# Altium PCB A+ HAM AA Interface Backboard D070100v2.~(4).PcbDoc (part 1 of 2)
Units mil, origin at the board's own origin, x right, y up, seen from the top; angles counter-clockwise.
Board outline 2600 x 10000 mil, 6 copper layers (Top Layer, InternalPlane1, MidLayer1, InternalPlane3, InternalPlane4, Bottom Layer), stack 92.2 mil thick; 10 components, 66 nets, 166 pads, 1741 vias.
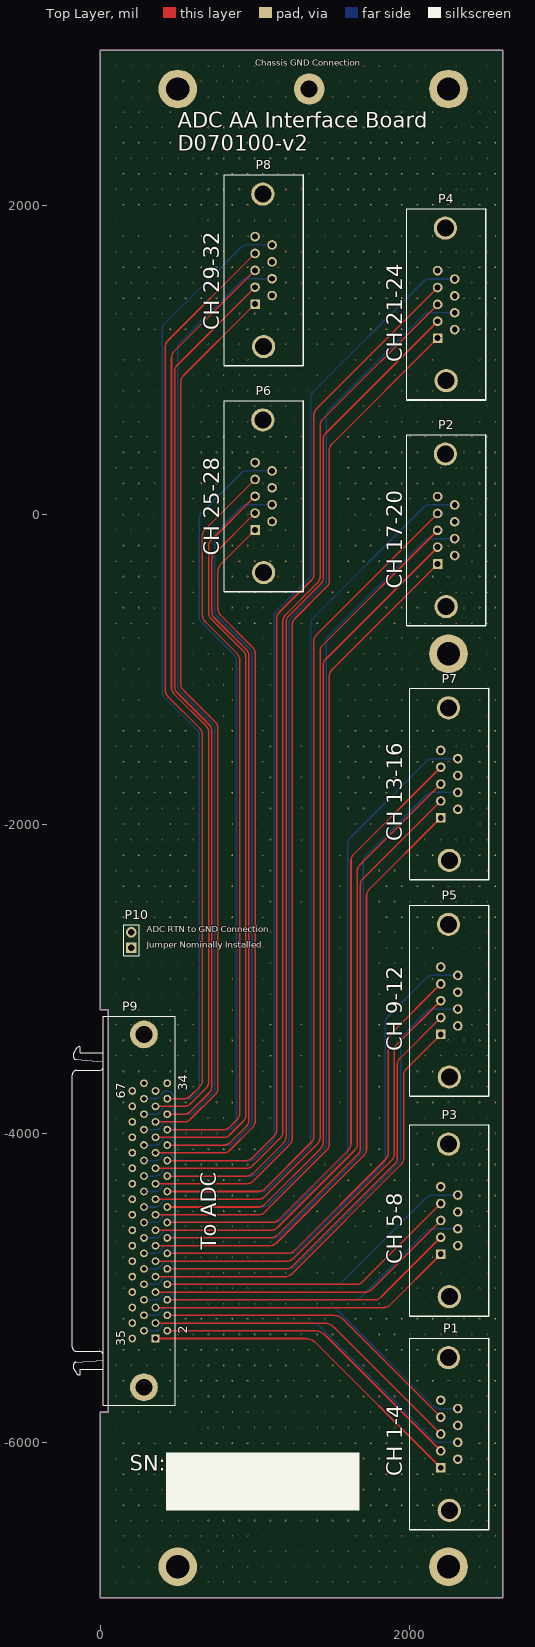
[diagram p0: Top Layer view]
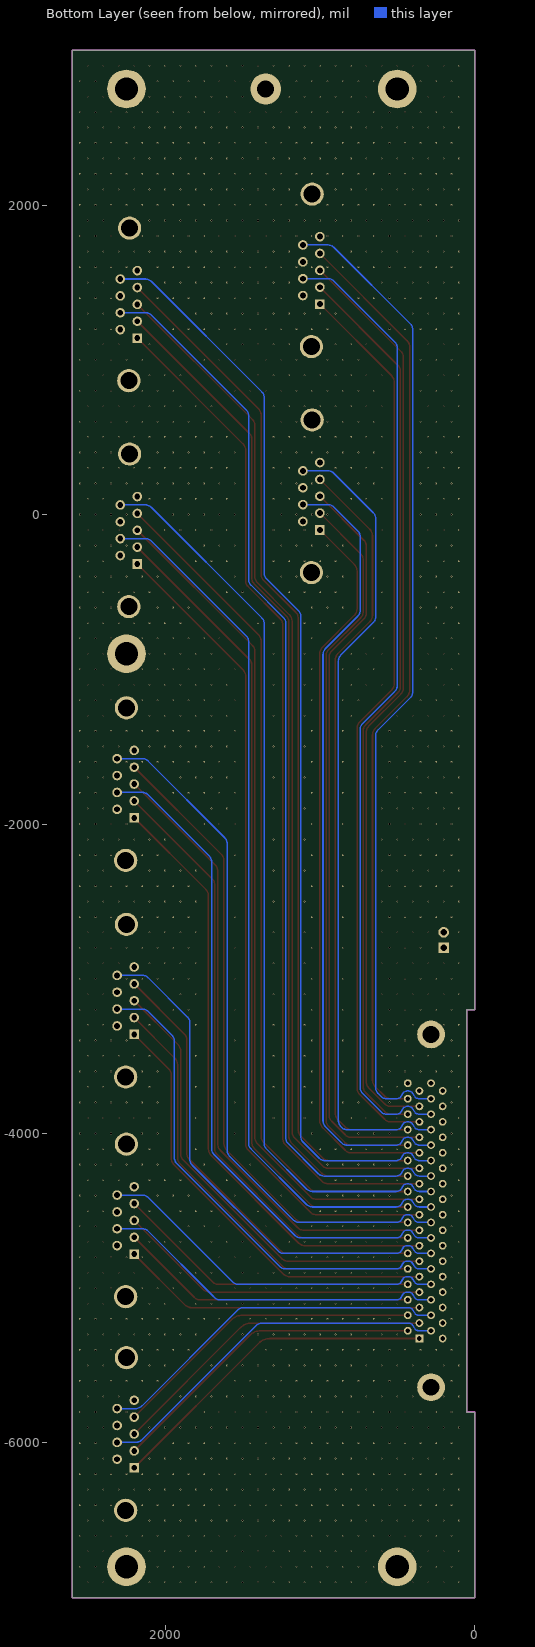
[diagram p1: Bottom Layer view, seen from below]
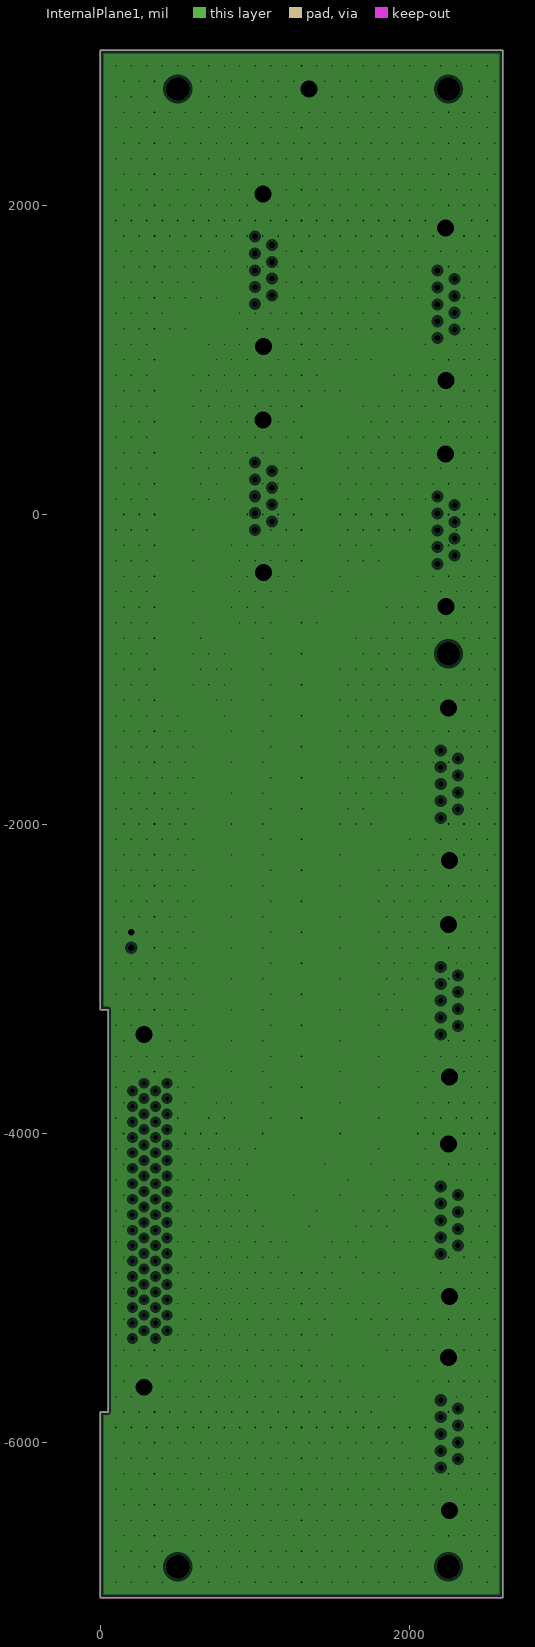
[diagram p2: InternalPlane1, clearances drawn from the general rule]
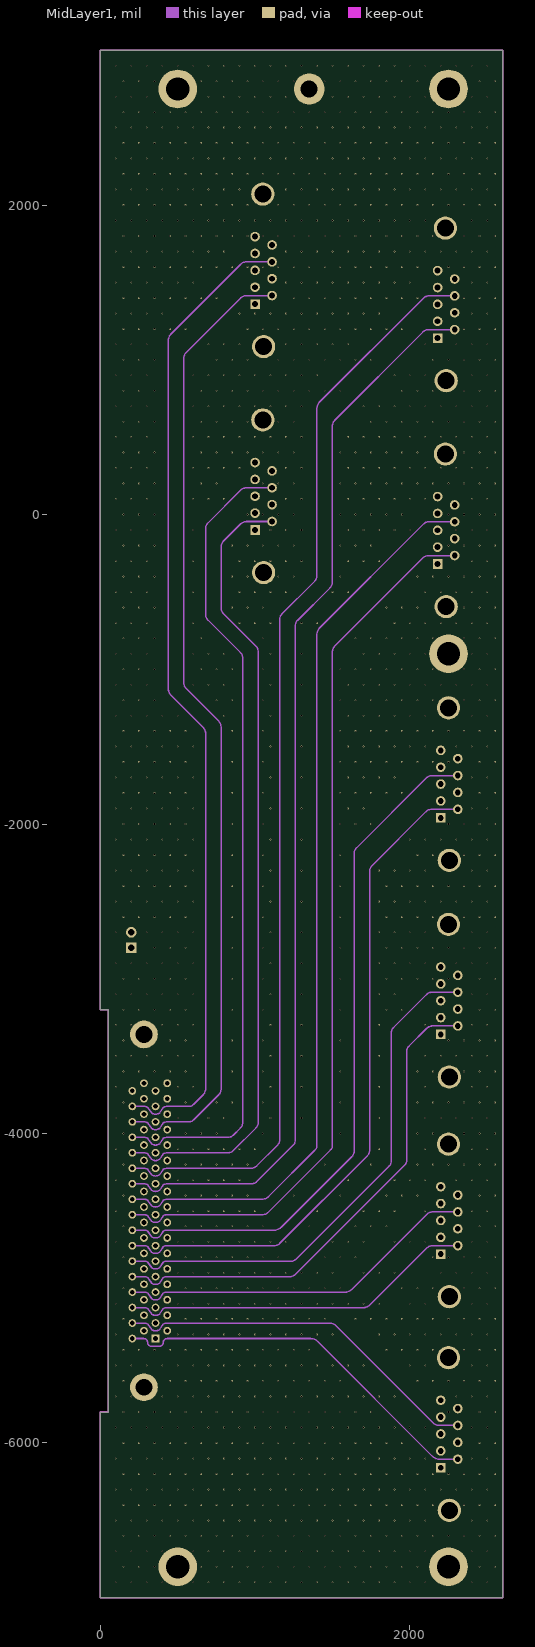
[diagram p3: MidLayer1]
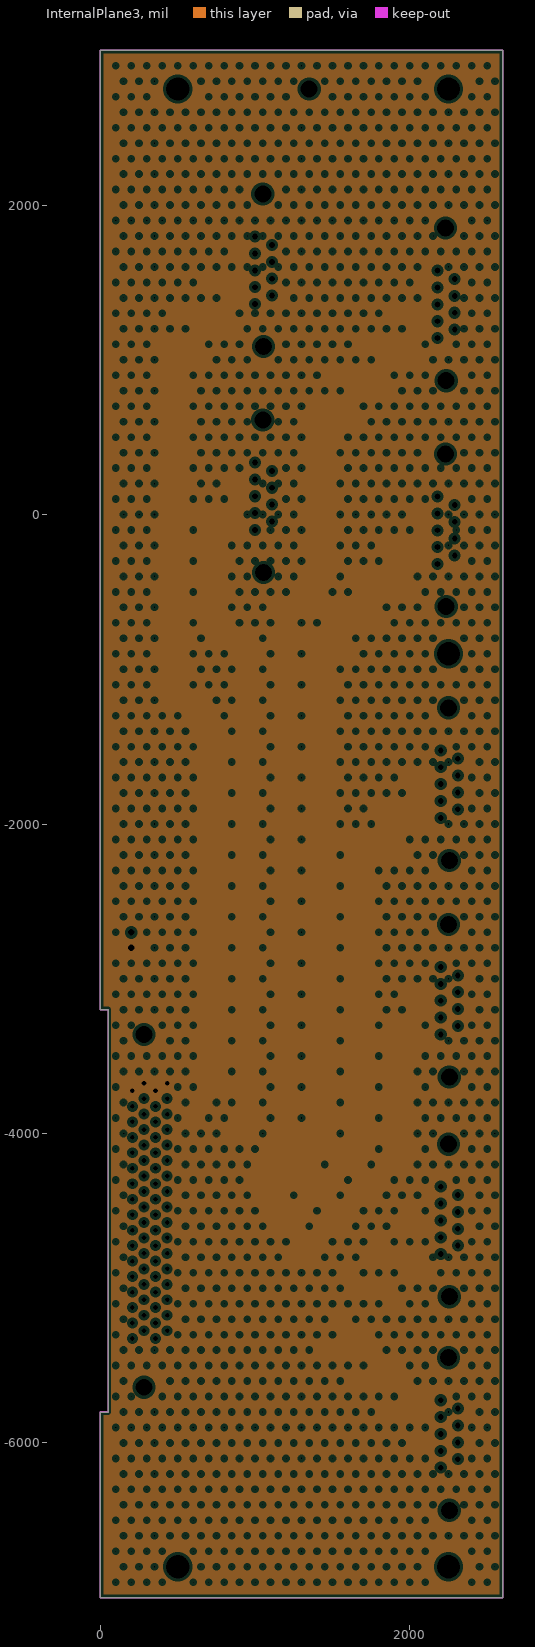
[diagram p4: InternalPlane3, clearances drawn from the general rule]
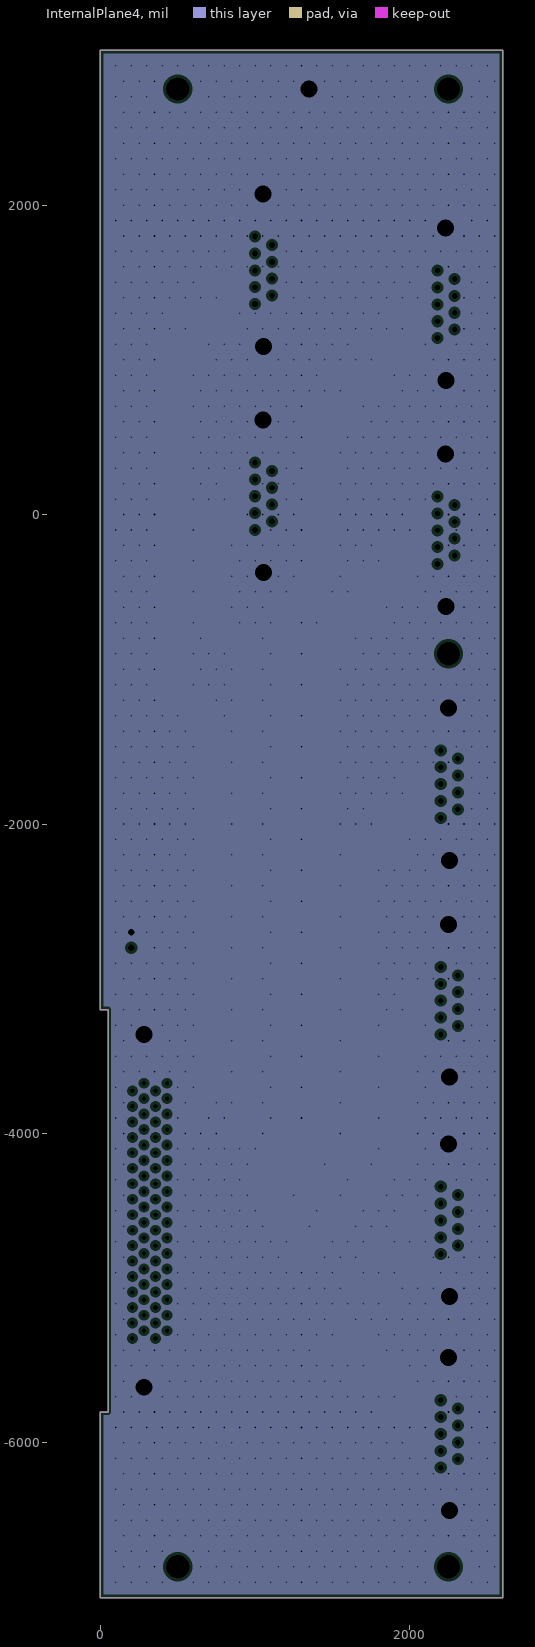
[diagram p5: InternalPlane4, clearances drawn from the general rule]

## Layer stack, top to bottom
Top Solder: solder mask 0.4, Solder Resist, Dk 3.5
Top Layer: signal copper 1.4
Dielectric1: core 15, FR-4, Dk 4.2
InternalPlane1: plane copper 1.4
Dielectric 6: prepreg 19.4, FR-4, Dk 4.2
MidLayer1: signal copper 1.4
Dielectric3: core 15, FR-4, Dk 4.2
InternalPlane3: plane copper 1.4
Dielectric4: prepreg 19.4, FR-4, Dk 4.2
InternalPlane4: plane copper 1.4
Dielectric5: core 15, FR-4, Dk 4.2
Bottom Layer: signal copper 1.4
Bottom Solder: solder mask 0.4, Solder Resist, Dk 3.5

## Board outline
0,-7000 0,-5800 50,-5800 50,-3200 0,-3200 0,3000 2600,3000 2600,-7000

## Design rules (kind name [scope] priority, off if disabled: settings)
Clearance [All] p1: gap=10 ignorepadtopadclearanceinfootprint=FALSE except(0: Arc-Hole Track-Hole SMDPad-Hole THPad-Hole Via-Hole Fill-Hole Poly-Hole Region-Hole Text-Hole)
FabricationTestPointUsage TestPointUsage [All] p1: valid=0 allowmultiple=FALSE
FabricationTestpoint Testpoint [All] p1: side=3 testpointundercomponent=TRUE minsize=40 maxsize=100 preferedsize=60 minholesize=0 maxholesize=40 preferedholesize=32 testpointgrid=1 allowsidetop=TRUE allowsidebottom=TRUE usegrid=TRUE gridtolerance=0.01
HoleSize [All] p1: absolutevalues=TRUE maxlimit=200 minlimit=1 maxpercent=80.000 minpercent=20.000
PlaneClearance [All] p1: clearance=20
PlaneConnect [All] p1: planeconnectstyle=Relief reliefexpansion=20 reliefentries=4 reliefconductorwidth=10 reliefairgap=10
PolygonConnect [All] p1: connectstyle=Relief reliefconductorwidth=10 reliefentries=4 polygonreliefangle="90 Angle" airgapwidth=10
RoutingVias [All] p1: holewidth=20 width=40 viastyle="Through Hole" minholewidth=20 minwidth=40 maxholewidth=28 maxwidth=50
SolderMaskExpansion [All] p1: expansion=4
Width [All] p1: maxlimit=100 minlimit=10 preferedwidth=10
25 further rules are at their usual default settings.

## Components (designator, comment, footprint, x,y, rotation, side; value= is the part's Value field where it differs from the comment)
P1 "D9M" DB9/M 2200,-6160 r270 top
P2 "D9M" DB9/M 2180,-320 r270 top
P3 "D9M" DB9/M 2200,-4780 r270 top
P4 "D9M" DB9/M 2180,1140 r270 top
P5 "D9M" DB9/M 2200,-3360 r270 top
P6 "D9M" DB9/M 1000,-100 r270 top
P7 "D9M" DB9/M 2200,-1960 r270 top
P8 "D9M" DB9/M 1000,1360 r270 top
P9 "787082-7" 787082-7 20,-4500 r90 top
P10 "Header 2" HDR1X2 200,-2800 r90 top

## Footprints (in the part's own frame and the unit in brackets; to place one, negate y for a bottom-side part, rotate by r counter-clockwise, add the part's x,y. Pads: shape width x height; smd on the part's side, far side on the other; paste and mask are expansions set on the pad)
787082-7 [mm] "Connector; D Subminiature 050 Series; 68 Position; Right Angle"
  rect 1.27x1.27 hole 0.762: 1(-20.955,-8.555)
  round 1.27 hole 0.762: 2(-19.685,-10.46) 3(-18.415,-8.555) 4(-17.145,-10.46) 5(-15.875,-8.555) 6(-14.605,-10.46) 7(-13.335,-8.555) 8(-12.065,-10.46) 9(-10.795,-8.555) 10(-9.525,-10.46) 11(-8.255,-8.555) 12(-6.985,-10.46) 13(-5.715,-8.555) 14(-4.445,-10.46) 15(-3.175,-8.555) 16(-1.905,-10.46) 17(-0.635,-8.555) 18(0.635,-10.46) 19(1.905,-8.555) 20(3.175,-10.46) 21(4.445,-8.555) 22(5.715,-10.46) 23(6.985,-8.555) 24(8.255,-10.46) 25(9.525,-8.555) 26(10.795,-10.46) 27(12.065,-8.555) 28(13.335,-10.46) 29(14.605,-8.555) 30(15.875,-10.46) 31(17.145,-8.555) 32(18.415,-10.46) 33(19.685,-8.555) 34(20.955,-10.46) 35(-20.955,-4.745) 36(-19.685,-6.65) 37(-18.415,-4.745) 38(-17.145,-6.65) 39(-15.875,-4.745) 40(-14.605,-6.65) 41(-13.335,-4.745) 42(-12.065,-6.65) 43(-10.795,-4.745) 44(-9.525,-6.65) 45(-8.255,-4.745) 46(-6.985,-6.65) 47(-5.715,-4.745) 48(-4.445,-6.65) 49(-3.175,-4.745) 50(-1.905,-6.65) 51(-0.635,-4.745) 52(0.635,-6.65) 53(1.905,-4.745) 54(3.175,-6.65) 55(4.445,-4.745) 56(5.715,-6.65) 57(6.985,-4.745) 58(8.255,-6.65) 59(9.525,-4.745) 60(10.795,-6.65) 61(12.065,-4.745) 62(13.335,-6.65) 63(14.605,-4.745) 64(15.875,-6.65) 65(17.145,-4.745) 66(18.415,-6.65) 67(19.685,-4.745) 68(20.955,-6.65)
  round 4.55 hole 2.77: 69(-28.955,-6.65) 70(28.955,-6.65)
  silkscreen extent -31.95,-11.76 31.95,5.11, body extent -31.94,-11.79 31.94,5.08, height 9.51
DB9/M [mil]
  round 150 hole 110: 0(-711,50) 0(275,55)
  rect 62x62 hole 38: 1(0,0)
  round 62 hole 38: 2(-109,0) 3(-218,0) 4(-327,0) 5(-436,0) 6(-55,110) 7(-164,110) 8(-273,110) 9(-382,110)
  silkscreen extent -836,-200 400,310, body extent -827,-194 389,302, height 470
HDR1X2 [mm] "Connector; Header; 2 Position"
  rect 1.75x1.75 hole 1.1: 1(0,0)
  round 1.75 hole 1.1: 2(2.54,0)
  silkscreen extent -1.27,-1.27 3.81,1.27, body extent -1.14,-1.19 3.68,1.15, height 10.8

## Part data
P1 P2 P3 P4 P5 P6 P7 P8: "9 Position D-Sub Plug, Male Pins Connector", Color=Black, Current Rating=6A, Flammability Rating="UL94 V-0", Manufacturer="TE Connectivity", Manufacturer Part Number=5747871-8, Max Operating Temperature=105°C, Max Supply Voltage (AC)=250V, Max Voltage Rating (DC)=250.25kV, Min Operating Temperature=-55°C, Package Quantity=17, Supplier Part Number 1=A32035-ND, Voltage Rating=125V
P9: "Receptacle Assembly, Shielded, Right Angle, AMPLIMITE", PackageDocument=13-Jan-2000
P10: "Header, 2-Pin", Part Number=WM4200

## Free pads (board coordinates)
  round 200 hole 110: 0(1350,2750)
  round 250 hole 150: 0(2250,-6800) 1(2250,2750) 2(500,2750) 3(500,-6800) 4(2250,-900)

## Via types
v1: diameter 12, hole 10, Top Layer to Bottom Layer, 1741 vias

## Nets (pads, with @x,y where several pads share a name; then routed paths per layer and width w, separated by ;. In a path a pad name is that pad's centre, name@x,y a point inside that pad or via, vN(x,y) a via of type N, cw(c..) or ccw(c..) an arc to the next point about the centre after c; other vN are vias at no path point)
GND: P1.0 P2.0 P3.0 P4.0 P5.0 P6.0 P7.0 P8.0 P9.69 P9.70 P10.2 pad.0@1350,2750
  other v1: 100,-6900 200,-6900 300,-6900 400,-6900 600,-6900 700,-6900 800,-6900 900,-6900 1000,-6900 1100,-6900 1200,-6900 1300,-6900 1400,-6900 1500,-6900 1600,-6900 1700,-6900 1800,-6900 1900,-6900 2000,-6900 2100,-6900 2400,-6900 2500,-6900 150,-6800 250,-6800 350,-6800 650,-6800 750,-6800 850,-6800 950,-6800 1050,-6800 1150,-6800 1250,-6800 1350,-6800 1450,-6800 1550,-6800 1650,-6800 1750,-6800 1850,-6800 1950,-6800 2050,-6800 2450,-6800 2550,-6800 100,-6700 200,-6700 300,-6700 400,-6700 600,-6700 700,-6700 800,-6700 900,-6700 1000,-6700 1100,-6700 1200,-6700 1300,-6700 1400,-6700 1500,-6700 1600,-6700 1700,-6700 1800,-6700 1900,-6700 2000,-6700 2100,-6700 2400,-6700 2500,-6700 150,-6600 250,-6600 350,-6600 450,-6600 550,-6600 650,-6600 750,-6600 850,-6600 950,-6600 1050,-6600 1150,-6600 1250,-6600 1350,-6600 1450,-6600 1550,-6600 1650,-6600 1750,-6600 1850,-6600 1950,-6600 2050,-6600 2150,-6600 2250,-6600 2350,-6600 2450,-6600 2550,-6600 100,-6500 200,-6500 300,-6500 400,-6500 500,-6500 600,-6500 700,-6500 800,-6500 900,-6500 1000,-6500 1100,-6500 1200,-6500 1300,-6500 1400,-6500 1500,-6500 1600,-6500 1700,-6500 1800,-6500 1900,-6500 2000,-6500 2100,-6500 2400,-6500 2500,-6500 150,-6400 250,-6400 350,-6400 450,-6400 550,-6400 650,-6400 750,-6400 850,-6400 950,-6400 1050,-6400 1150,-6400 1250,-6400 1350,-6400 1450,-6400 1550,-6400 1650,-6400 1750,-6400 1850,-6400 1950,-6400 2050,-6400 2150,-6400 2350,-6400 2450,-6400 2550,-6400 100,-6300 200,-6300 300,-6300 400,-6300 500,-6300 600,-6300 700,-6300 800,-6300 900,-6300 1000,-6300 1100,-6300 1200,-6300 1300,-6300 1400,-6300 1500,-6300 1600,-6300 1700,-6300 1800,-6300 1900,-6300 2000,-6300 2100,-6300 2200,-6300 2300,-6300 2400,-6300 2500,-6300 150,-6200 250,-6200 350,-6200 450,-6200 550,-6200 650,-6200 750,-6200 850,-6200 950,-6200 1050,-6200 1150,-6200 1250,-6200 1350,-6200 1450,-6200 1550,-6200 1650,-6200 1750,-6200 1850,-6200 1950,-6200 2050,-6200 2150,-6200 2250,-6200 2350,-6200 2450,-6200 2550,-6200 100,-6100 200,-6100 300,-6100 400,-6100 500,-6100 600,-6100 700,-6100 800,-6100 900,-6100 1000,-6100 1100,-6100 1200,-6100 1300,-6100 1400,-6100 1500,-6100 1600,-6100 1700,-6100 1800,-6100 1900,-6100 2000,-6100 2100,-6100 2400,-6100 2500,-6100 150,-6000 250,-6000 350,-6000 450,-6000 550,-6000 650,-6000 750,-6000 850,-6000 950,-6000 1050,-6000 1150,-6000 1250,-6000 1350,-6000 1450,-6000 1550,-6000 1650,-6000 1750,-6000 1850,-6000 1950,-6000 2450,-6000 2550,-6000 100,-5900 200,-5900 300,-5900 400,-5900 500,-5900 600,-5900 700,-5900 800,-5900 900,-5900 1000,-5900 1100,-5900 1200,-5900 1300,-5900 1400,-5900 1500,-5900 1600,-5900 1700,-5900 1800,-5900 1900,-5900 2000,-5900 2100,-5900 2400,-5900 2500,-5900 150,-5800 250,-5800 350,-5800 450,-5800 550,-5800 650,-5800 750,-5800 850,-5800 950,-5800 1050,-5800 1150,-5800 1250,-5800 1350,-5800 1450,-5800 1550,-5800 1650,-5800 1750,-5800 2250,-5800 2450,-5800 2550,-5800 100,-5700 200,-5700 400,-5700 500,-5700 600,-5700 700,-5700 800,-5700 900,-5700 1000,-5700 1100,-5700 1200,-5700 1300,-5700 1400,-5700 1500,-5700 1600,-5700 1700,-5700 1800,-5700 1900,-5700 2300,-5700 2400,-5700 2500,-5700 150,-5600 450,-5600 550,-5600 650,-5600 750,-5600 850,-5600 950,-5600 1050,-5600 1150,-5600 1250,-5600 1350,-5600 1450,-5600 1550,-5600 2050,-5600 2150,-5600 2250,-5600 2350,-5600 2450,-5600 2550,-5600 100,-5500 200,-5500 300,-5500 400,-5500 500,-5500 600,-5500 700,-5500 800,-5500 900,-5500 1000,-5500 1100,-5500 1200,-5500 1300,-5500 1400,-5500 1500,-5500 1600,-5500 1700,-5500 2000,-5500 2100,-5500 2400,-5500 2500,-5500 150,-5400 250,-5400 350,-5400 450,-5400 550,-5400 650,-5400 750,-5400 850,-5400 950,-5400 1050,-5400 1150,-5400 1250,-5400 1350,-5400 1850,-5400 1950,-5400 2050,-5400 2150,-5400 2350,-5400 2450,-5400 2550,-5400 100,-5300 500,-5300 600,-5300 700,-5300 800,-5300 900,-5300 1000,-5300 1100,-5300 1200,-5300 1300,-5300 1400,-5300 1500,-5300 1800,-5300 1900,-5300 2000,-5300 2100,-5300 2200,-5300 2300,-5300 2400,-5300 2500,-5300 150,-5200 550,-5200 650,-5200 750,-5200 850,-5200 950,-5200 1050,-5200 1150,-5200 1250,-5200 1350,-5200 1450,-5200 1650,-5200 1750,-5200 1850,-5200 1950,-5200 2050,-5200 2150,-5200 2250,-5200 2350,-5200 2450,-5200 2550,-5200 100,-5100 500,-5100 600,-5100 700,-5100 800,-5100 900,-5100 1000,-5100 1100,-5100 1200,-5100 1300,-5100 1400,-5100 1500,-5100 1600,-5100 1700,-5100 1800,-5100 2000,-5100 2100,-5100 2400,-5100 2500,-5100 150,-5000 550,-5000 650,-5000 750,-5000 850,-5000 950,-5000 1050,-5000 1150,-5000 1250,-5000 1350,-5000 1450,-5000 1550,-5000 1950,-5000 2050,-5000 2150,-5000 2350,-5000 2450,-5000 2550,-5000 100,-4900 500,-4900 600,-4900 700,-4900 800,-4900 900,-4900 1000,-4900 1100,-4900 1200,-4900 1300,-4900 1400,-4900 1500,-4900 1700,-4900 1800,-4900 1900,-4900 2200,-4900 2300,-4900 2400,-4900 2500,-4900 150,-4800 550,-4800 650,-4800 750,-4800 850,-4800 950,-4800 1050,-4800 1150,-4800 1450,-4800 1550,-4800 1650,-4800 2150,-4800 2250,-4800 2350,-4800 2450,-4800 2550,-4800 100,-4700 500,-4700 600,-4700 700,-4700 800,-4700 900,-4700 1000,-4700 1100,-4700 1200,-4700 1500,-4700 1600,-4700 1700,-4700 1900,-4700 2000,-4700 2100,-4700 2400,-4700 2500,-4700 150,-4600 550,-4600 650,-4600 750,-4600 850,-4600 950,-4600 1050,-4600 1350,-4600 1650,-4600 1750,-4600 1850,-4600 2450,-4600 2550,-4600 100,-4500 500,-4500 600,-4500 700,-4500 800,-4500 900,-4500 1000,-4500 1400,-4500 1700,-4500 1800,-4500 1900,-4500 2100,-4500 2400,-4500 2500,-4500 150,-4400 550,-4400 650,-4400 750,-4400 850,-4400 950,-4400 1250,-4400 1550,-4400 1850,-4400 1950,-4400 2050,-4400 2450,-4400 2550,-4400 100,-4300 500,-4300 600,-4300 700,-4300 800,-4300 900,-4300 1600,-4300 1900,-4300 2000,-4300 2100,-4300 2300,-4300 2400,-4300 2500,-4300 150,-4200 550,-4200 650,-4200 750,-4200 850,-4200 950,-4200 1450,-4200 1750,-4200 2050,-4200 2150,-4200 2250,-4200 2350,-4200 2450,-4200 2550,-4200 100,-4100 500,-4100 600,-4100 700,-4100 800,-4100 900,-4100 1000,-4100 1800,-4100 2100,-4100 2400,-4100 2500,-4100 150,-4000 550,-4000 650,-4000 750,-4000 1050,-4000 1550,-4000 2050,-4000 2150,-4000 2350,-4000 2450,-4000 2550,-4000 100,-3900 500,-3900 700,-3900 800,-3900 1100,-3900 1300,-3900 1800,-3900 2100,-3900 2200,-3900 2300,-3900 2400,-3900 2500,-3900 150,-3800 550,-3800 750,-3800 850,-3800 1050,-3800 1550,-3800 2050,-3800 2150,-3800 2250,-3800 2350,-3800 2450,-3800 2550,-3800 100,-3700 500,-3700 600,-3700 1100,-3700 1300,-3700 1800,-3700 2100,-3700 2400,-3700 2500,-3700 150,-3600 250,-3600 350,-3600 450,-3600 550,-3600 850,-3600 1050,-3600 1550,-3600 2050,-3600 2150,-3600 2350,-3600 2450,-3600 2550,-3600 100,-3500 200,-3500 300,-3500 400,-3500 500,-3500 600,-3500 1100,-3500 1300,-3500 1800,-3500 2100,-3500 2200,-3500 2300,-3500 2400,-3500 2500,-3500 150,-3400 450,-3400 550,-3400 850,-3400 1050,-3400 1550,-3400 2250,-3400 2350,-3400 2450,-3400 2550,-3400 100,-3300 200,-3300 400,-3300 500,-3300 600,-3300 1100,-3300 1300,-3300 1800,-3300 2100,-3300 2400,-3300 2500,-3300 150,-3200 250,-3200 350,-3200 450,-3200 550,-3200 850,-3200 1050,-3200 1550,-3200 1850,-3200 1950,-3200 2450,-3200 2550,-3200 100,-3100 200,-3100 300,-3100 400,-3100 500,-3100 600,-3100 1100,-3100 1300,-3100 1800,-3100 1900,-3100 2400,-3100 2500,-3100 150,-3000 250,-3000 350,-3000 450,-3000 550,-3000 850,-3000 1050,-3000 1550,-3000 1850,-3000 1950,-3000 2050,-3000 2150,-3000 2250,-3000 2450,-3000 2550,-3000 100,-2900 200,-2900 300,-2900 400,-2900 500,-2900 600,-2900 1100,-2900 1300,-2900 1800,-2900 1900,-2900 2000,-2900 2100,-2900 2300,-2900 2400,-2900 2500,-2900 350,-2800 450,-2800 550,-2800 850,-2800 1050,-2800 1550,-2800 1850,-2800 1950,-2800 2050,-2800 2150,-2800 2250,-2800 2350,-2800 2450,-2800 2550,-2800 100,-2700 300,-2700 400,-2700 500,-2700 600,-2700 1100,-2700 1300,-2700 1800,-2700 1900,-2700 2000,-2700 2100,-2700 2400,-2700 2500,-2700 150,-2600 250,-2600 350,-2600 450,-2600 550,-2600 850,-2600 1050,-2600 1550,-2600 1850,-2600 1950,-2600 2050,-2600 2150,-2600 2350,-2600 2450,-2600 2550,-2600 100,-2500 200,-2500 300,-2500 400,-2500 500,-2500 600,-2500 1100,-2500 1300,-2500 1800,-2500 1900,-2500 2000,-2500 2100,-2500 2200,-2500 2300,-2500 2400,-2500 2500,-2500 150,-2400 250,-2400 350,-2400 450,-2400 550,-2400 850,-2400 1050,-2400 1550,-2400 1850,-2400 1950,-2400 2050,-2400 2150,-2400 2250,-2400 2350,-2400 2450,-2400 2550,-2400 100,-2300 200,-2300 300,-2300 400,-2300 500,-2300 600,-2300 1100,-2300 1300,-2300 1800,-2300 1900,-2300 2000,-2300 2100,-2300 2400,-2300 2500,-2300 150,-2200 250,-2200 350,-2200 450,-2200 550,-2200 850,-2200 1050,-2200 1550,-2200 2050,-2200 2150,-2200 2350,-2200 2450,-2200 2550,-2200 100,-2100 200,-2100 300,-2100 400,-2100 500,-2100 600,-2100 1100,-2100 1300,-2100 2000,-2100 2100,-2100 2200,-2100 2300,-2100 2400,-2100 2500,-2100 150,-2000 250,-2000 350,-2000 450,-2000 550,-2000 850,-2000 1050,-2000 1550,-2000 1650,-2000 1750,-2000 2250,-2000 2350,-2000 2450,-2000 2550,-2000 100,-1900 200,-1900 300,-1900 400,-1900 500,-1900 600,-1900 1100,-1900 1300,-1900 1600,-1900 1700,-1900 2400,-1900 2500,-1900 150,-1800 250,-1800 350,-1800 450,-1800 550,-1800 850,-1800 1050,-1800 1550,-1800 1650,-1800 1750,-1800 1850,-1800 1950,-1800 2450,-1800 2550,-1800 100,-1700 200,-1700 300,-1700 400,-1700 500,-1700 600,-1700 1100,-1700 1300,-1700 1600,-1700 1700,-1700 1800,-1700 1900,-1700 2400,-1700 2500,-1700 150,-1600 250,-1600 350,-1600 450,-1600 550,-1600 850,-1600 1050,-1600 1550,-1600 1650,-1600 1750,-1600 1850,-1600 1950,-1600 2050,-1600 2150,-1600 2250,-1600 2450,-1600 2550,-1600 100,-1500 200,-1500 300,-1500 400,-1500 500,-1500 600,-1500 1100,-1500 1300,-1500 1600,-1500 1700,-1500 1800,-1500 1900,-1500 2000,-1500 2100,-1500 2300,-1500 2400,-1500 2500,-1500 150,-1400 250,-1400 350,-1400 450,-1400 550,-1400 850,-1400 1050,-1400 1550,-1400 1650,-1400 1750,-1400 1850,-1400 1950,-1400 2050,-1400 2150,-1400 2250,-1400 2350,-1400 2450,-1400 2550,-1400 100,-1300 200,-1300 300,-1300 400,-1300 500,-1300 800,-1300 1100,-1300 1300,-1300 1600,-1300 1700,-1300 1800,-1300 1900,-1300 2000,-1300 2100,-1300 2400,-1300 2500,-1300 150,-1200 250,-1200 350,-1200 750,-1200 850,-1200 1050,-1200 1550,-1200 1650,-1200 1750,-1200 1850,-1200 1950,-1200 2050,-1200 2150,-1200 2350,-1200 2450,-1200 2550,-1200 100,-1100 200,-1100 300,-1100 600,-1100 700,-1100 800,-1100 1100,-1100 1300,-1100 1600,-1100 1700,-1100 1800,-1100 1900,-1100 2000,-1100 2100,-1100 2200,-1100 2300,-1100 2400,-1100 2500,-1100 150,-1000 250,-1000 350,-1000 650,-1000 750,-1000 850,-1000 1050,-1000 1550,-1000 1650,-1000 1750,-1000 1850,-1000 1950,-1000 2050,-1000 2150,-1000 2350,-1000 2450,-1000 2550,-1000 100,-900 200,-900 300,-900 600,-900 700,-900 800,-900 1100,-900 1300,-900 1700,-900 1800,-900 1900,-900 2000,-900 2100,-900 2400,-900 2500,-900 150,-800 250,-800 350,-800 650,-800 1050,-800 1650,-800 1750,-800 1850,-800 1950,-800 2050,-800 2150,-800 2350,-800 2450,-800 2550,-800 100,-700 200,-700 300,-700 600,-700 900,-700 1000,-700 1100,-700 1300,-700 1400,-700 1900,-700 2000,-700 2100,-700 2200,-700 2300,-700 2400,-700 2500,-700 150,-600 250,-600 350,-600 850,-600 950,-600 1050,-600 1850,-600 1950,-600 2050,-600 2350,-600 2450,-600 2550,-600 100,-500 200,-500 300,-500 600,-500 900,-500 1000,-500 1100,-500 1200,-500 1500,-500 1600,-500 2100,-500 2200,-500 2300,-500 2400,-500 2500,-500 150,-400 250,-400 350,-400 850,-400 950,-400 1150,-400 1250,-400 1550,-400 2050,-400 2150,-400 2250,-400 2350,-400 2450,-400 2550,-400 100,-300 200,-300 300,-300 600,-300 900,-300 1000,-300 1100,-300 1200,-300 1300,-300 1600,-300 1700,-300 1800,-300 2400,-300 2500,-300 150,-200 250,-200 350,-200 850,-200 950,-200 1050,-200 1150,-200 1250,-200 1550,-200 1650,-200 1750,-200 2250,-200 2350,-200 2450,-200 2550,-200 100,-100 200,-100 300,-100 600,-100 1100,-100 1200,-100 1300,-100 1600,-100 1700,-100 1800,-100 1900,-100 2000,-100 2300,-100 2400,-100 2500,-100 150,0 250,0 350,0 950,0 1050,0 1150,0 1250,0 1550,0 1650,0 1750,0 1850,0 1950,0 2250,0 2350,0 2450,0 2550,0 100,100 200,100 300,100 600,100 700,100 800,100 1200,100 1300,100 1600,100 1700,100 1800,100 1900,100 2000,100 2100,100 2400,100 2500,100 150,200 250,200 350,200 650,200 750,200 1050,200 1150,200 1250,200 1550,200 1650,200 1750,200 1850,200 1950,200 2050,200 2150,200 2250,200 2350,200 2450,200 2550,200 100,300 200,300 300,300 600,300 700,300 800,300 900,300 1200,300 1300,300 1600,300 1700,300 1800,300 1900,300 2000,300 2100,300 2200,300 2300,300 2400,300 2500,300 150,400 250,400 350,400 650,400 750,400 850,400 950,400 1050,400 1150,400 1250,400 1550,400 1650,400 1750,400 1850,400 1950,400 2050,400 2350,400 2450,400 2550,400 100,500 200,500 300,500 600,500 700,500 800,500 900,500 1000,500 1100,500 1200,500 1300,500 1600,500 1700,500 1800,500 1900,500 2000,500 2100,500 2200,500 2300,500 2400,500 2500,500 150,600 250,600 350,600 650,600 750,600 850,600 950,600 1150,600 1250,600 1750,600 1850,600 1950,600 2050,600 2150,600 2250,600 2350,600 2450,600 2550,600 100,700 200,700 300,700 600,700 700,700 800,700 900,700 1000,700 1100,700 1200,700 1300,700 1700,700 1800,700 1900,700 2000,700 2100,700 2200,700 2300,700 2400,700 2500,700 150,800 250,800 350,800 650,800 750,800 850,800 950,800 1050,800 1150,800 1250,800 1350,800 1450,800 1550,800 1950,800 2050,800 2150,800 2350,800 2450,800 2550,800 100,900 200,900 300,900 600,900 700,900 800,900 900,900 1000,900 1100,900 1200,900 1300,900 1400,900 1900,900 2000,900 2100,900 2400,900 2500,900 150,1000 250,1000 350,1000 750,1000 850,1000 950,1000 1150,1000 1250,1000 1350,1000 1450,1000 1550,1000 1650,1000 1750,1000 2150,1000 2250,1000 2350,1000 2450,1000 2550,1000 100,1100 200,1100 300,1100 700,1100 800,1100 900,1100 1200,1100 1300,1100 1400,1100 1500,1100 1600,1100 2100,1100 2300,1100 2400,1100 2500,1100 150,1200 250,1200 350,1200 450,1200 550,1200 950,1200 1050,1200 1150,1200 1250,1200 1350,1200 1450,1200 1550,1200 1650,1200 1750,1200 1850,1200 1950,1200 2350,1200 2450,1200 2550,1200 100,1300 200,1300 300,1300 400,1300 900,1300 1000,1300 1100,1300 1200,1300 1300,1300 1400,1300 1500,1300 1600,1300 1700,1300 1800,1300 2400,1300 2500,1300 150,1400 250,1400 350,1400 450,1400 550,1400 650,1400 750,1400 1250,1400 1350,1400 1450,1400 1550,1400 1650,1400 1750,1400 1850,1400 1950,1400 2050,1400 2350,1400 2450,1400 2550,1400 100,1500 200,1500 300,1500 400,1500 500,1500 600,1500 1200,1500 1300,1500 1400,1500 1500,1500 1600,1500 1700,1500 1800,1500 1900,1500 2000,1500 2400,1500 2500,1500 150,1600 250,1600 350,1600 450,1600 550,1600 650,1600 750,1600 850,1600 950,1600 1050,1600 1150,1600 1250,1600 1350,1600 1450,1600 1550,1600 1650,1600 1750,1600 1850,1600 1950,1600 2050,1600 2250,1600 2350,1600 2450,1600 2550,1600 100,1700 200,1700 300,1700 400,1700 500,1700 600,1700 700,1700 800,1700 1200,1700 1300,1700 1400,1700 1500,1700 1600,1700 1700,1700 1800,1700 1900,1700 2000,1700 2100,1700 2200,1700 2300,1700 2400,1700 2500,1700 150,1800 250,1800 350,1800 450,1800 550,1800 650,1800 750,1800 850,1800 950,1800 1050,1800 1150,1800 1250,1800 1350,1800 1450,1800 1550,1800 1650,1800 1750,1800 1850,1800 1950,1800 2050,1800 2150,1800 2350,1800 2450,1800 2550,1800 100,1900 200,1900 300,1900 400,1900 500,1900 600,1900 700,1900 800,1900 900,1900 1000,1900 1100,1900 1200,1900 1300,1900 1400,1900 1500,1900 1600,1900 1700,1900 1800,1900 1900,1900 2000,1900 2100,1900 2400,1900 2500,1900 150,2000 250,2000 350,2000 450,2000 550,2000 650,2000 750,2000 850,2000 950,2000 1150,2000 1250,2000 1350,2000 1450,2000 1550,2000 1650,2000 1750,2000 1850,2000 1950,2000 2050,2000 2150,2000 2250,2000 2350,2000 2450,2000 2550,2000 100,2100 200,2100 300,2100 400,2100 500,2100 600,2100 700,2100 800,2100 900,2100 1200,2100 1300,2100 1400,2100 1500,2100 1600,2100 1700,2100 1800,2100 1900,2100 2000,2100 2100,2100 2200,2100 2300,2100 2400,2100 2500,2100 150,2200 250,2200 350,2200 450,2200 550,2200 650,2200 750,2200 850,2200 950,2200 1050,2200 1150,2200 1250,2200 1350,2200 1450,2200 1550,2200 1650,2200 1750,2200 1850,2200 1950,2200 2050,2200 2150,2200 2250,2200 2350,2200 2450,2200 2550,2200 100,2300 200,2300 300,2300 400,2300 500,2300 600,2300 700,2300 800,2300 900,2300 1000,2300 1100,2300 1200,2300 1300,2300 1400,2300 1500,2300 1600,2300 1700,2300 1800,2300 1900,2300 2000,2300 2100,2300 2200,2300 2300,2300 2400,2300 2500,2300 150,2400 250,2400 350,2400 450,2400 550,2400 650,2400 750,2400 850,2400 950,2400 1050,2400 1150,2400 1250,2400 1350,2400 1450,2400 1550,2400 1650,2400 1750,2400 1850,2400 1950,2400 2050,2400 2150,2400 2250,2400 2350,2400 2450,2400 2550,2400 100,2500 200,2500 300,2500 400,2500 500,2500 600,2500 700,2500 800,2500 900,2500 1000,2500 1100,2500 1200,2500 1300,2500 1400,2500 1500,2500 1600,2500 1700,2500 1800,2500 1900,2500 2000,2500 2100,2500 2200,2500 2300,2500 2400,2500 2500,2500 150,2600 250,2600 350,2600 450,2600 550,2600 650,2600 750,2600 850,2600 950,2600 1050,2600 1150,2600 1250,2600 1350,2600 1450,2600 1550,2600 1650,2600 1750,2600 1850,2600 1950,2600 2050,2600 2150,2600 2250,2600 2350,2600 2450,2600 2550,2600 100,2700 200,2700 300,2700 700,2700 800,2700 900,2700 1000,2700 1100,2700 1200,2700 1500,2700 1600,2700 1700,2700 1800,2700 1900,2700 2000,2700 2100,2700 2400,2700 2500,2700 150,2800 250,2800 350,2800 650,2800 750,2800 850,2800 950,2800 1050,2800 1150,2800 1250,2800 1450,2800 1550,2800 1650,2800 1750,2800 1850,2800 1950,2800 2050,2800 2450,2800 2550,2800 100,2900 200,2900 300,2900 400,2900 500,2900 600,2900 700,2900 800,2900 900,2900 1000,2900 1100,2900 1200,2900 1300,2900 1400,2900 1500,2900 1600,2900 1700,2900 1800,2900 1900,2900 2000,2900 2100,2900 2200,2900 2300,2900 2400,2900 2500,2900
OUTPUTN1: P1.6 P9.35 | length 2478.2
  MidLayer1 w10: P9.35@206.81,-5325 280,-5325 cw(c280,-5350) 305,-5350 ccw(c330,-5350) 330,-5375 356.81,-5375 381.81,-5375 ccw(c381.81,-5350) 406.81,-5350 cw(c431.81,-5350) 431.81,-5325 1360,-5325 cw(c1360,-5385.36) 1402.62,-5342.62 ; P1.6@2310,-6105 2190,-6105 cw(c2190,-6044.64) 2147.32,-6087.32 1402.68,-5342.68 ; 1402.62,-5342.62 cw(c1360,-5385.36) 1402.68,-5342.68 ; 1402.62,-5342.62 1402.68,-5342.68
OUTPUTN2: P1.7 P9.36 | length 2386.2
  Top Layer w10: P1.7@2310,-6020 P1.7@2310,-5996
  Bottom Layer w10: P9.36@281.81,-5275 355,-5275 ; 356.81,-5275 ccw(c356.81,-5225) 382.3,-5268.01 ; 382.44,-5267.93 406.08,-5232.13 cw(c431.81,-5275) 431.81,-5225 1370,-5225 cw(c1370,-5285.35) 1412.65,-5242.65 2148.35,-5978.35 ccw(c2191,-5935.65) 2191,-5996 P1.7@2310,-5996
OUTPUTN3: P1.8 P9.37 | length 2414.3
  MidLayer1 w10: P9.37@206.81,-5225 280,-5225 ; 281.81,-5225 cw(c281.81,-5275) 307.3,-5231.99 cw(c281.81,-5275) 307.44,-5232.07 ; 307.28,-5231.82 307.44,-5232.07 ; 406.18,-5232.07 382.54,-5267.87 cw(c356.81,-5225) 356.81,-5275 cw(c356.81,-5225) 331.08,-5267.87 307.44,-5232.07 ; 406.32,-5231.99 cw(c431.81,-5275) 431.81,-5225 1480,-5225 cw(c1480,-5285.36) 1522.68,-5242.68 2149.32,-5869.32 ; P1.8@2310,-5887 2192,-5887 cw(c2192,-5826.64) 2149.38,-5869.38 ; 2149.32,-5869.32 ccw(c2192,-5826.64) 2149.38,-5869.38 ; 2149.32,-5869.32 2149.38,-5869.38
OUTPUTN4: P1.9 P9.38 | length 2313.4
  Bottom Layer w10: P9.38@281.81,-5175 355,-5175 ; 356.81,-5175 ccw(c356.81,-5125) 382.3,-5168.01 ; 382.44,-5167.93 406.08,-5132.13 cw(c431.81,-5175) 431.81,-5125 1490,-5125 cw(c1490,-5185.35) 1532.65,-5142.65 ; 1532.68,-5142.68 1535,-5145 2150.35,-5760.35 ccw(c2193,-5717.65) 2193,-5778 P1.9@2310,-5778
OUTPUTN5: P3.6 P9.39 | length 2310.9
  MidLayer1 w10: P9.39@206.81,-5125 280,-5125 ; 281.81,-5125 cw(c281.81,-5175) 307.3,-5131.99 ; 406.18,-5132.07 382.54,-5167.87 cw(c356.81,-5125) 356.81,-5175 cw(c356.81,-5125) 331.08,-5167.87 307.44,-5132.07 ; 406.32,-5131.99 cw(c431.81,-5175) 431.81,-5125 1703.79,-5125 ccw(c1703.79,-5073.79) 1739.98,-5110.02 2108,-4742 ; 2110.86,-4739.14 2108,-4742 ; P3.6@2310,-4725 2145,-4725 ccw(c2145,-4773.28) 2110.88,-4739.12 2108,-4742 ; 307.3,-5131.99 cw(c281.81,-5175) 307.44,-5132.07 ; 307.3,-5131.99 cw(c356.81,-5125) 307.28,-5131.82 307.44,-5132.07
OUTPUTN6: P3.7 P9.40 | length 2256.1
  Bottom Layer w10: P9.40@281.81,-5075 355,-5075 ; 356.81,-5075 ccw(c356.81,-5025) 382.3,-5068.01 ; 481.18,-5067.93 457.54,-5032.13 ccw(c431.81,-5075) 431.81,-5025 ccw(c431.81,-5075) 406.08,-5032.13 382.44,-5067.93 ; 481.32,-5068.01 ccw(c506.81,-5025) 506.81,-5075 1645,-5075 ccw(c1645,-5024.3) 1680.83,-5060.17 1686,-5055 2110.17,-4630.83 cw(c2146,-4666.7) 2146,-4616 P3.7@2310,-4616 ; 382.3,-5068.01 ccw(c356.81,-5025) 382.44,-5067.93 ; 382.3,-5068.01 ccw(c431.81,-5075) 382.28,-5068.18 382.44,-5067.93
OUTPUTN7: P3.8 P9.41 | length 2362.5
  MidLayer1 w10: P9.41@206.81,-5025 280,-5025 ; 281.81,-5025 cw(c281.81,-5075) 307.3,-5031.99 ; 406.18,-5032.07 382.54,-5067.87 cw(c356.81,-5025) 356.81,-5075 cw(c356.81,-5025) 331.08,-5067.87 307.44,-5032.07 ; 406.32,-5031.99 cw(c431.81,-5075) 431.81,-5025 1585,-5025 ccw(c1585,-4971.89) 1622.54,-5009.46 2106,-4526 ; 2110.86,-4521.14 2106,-4526 ; P3.8@2310,-4507 2145,-4507 ccw(c2145,-4555.28) 2110.88,-4521.12 2106,-4526 ; 307.3,-5031.99 cw(c281.81,-5075) 307.44,-5032.07 ; 307.3,-5031.99 cw(c356.81,-5025) 307.28,-5031.82 307.44,-5032.07
OUTPUTN8: P3.9 P9.42 | length 2305
  Bottom Layer w10: P9.42@281.81,-4975 355,-4975 ; 356.81,-4975 ccw(c356.81,-4925) 382.3,-4968.01 ; 481.18,-4967.93 457.54,-4932.13 ccw(c431.81,-4975) 431.81,-4925 ccw(c431.81,-4975) 406.08,-4932.13 382.44,-4967.93 ; 481.32,-4968.01 ccw(c506.81,-4925) 506.81,-4975 1527,-4975 ccw(c1527,-4924.3) 1562.83,-4960.17 2110.17,-4412.83 cw(c2146,-4448.7) 2146,-4398 P3.9@2310,-4398 ; 382.3,-4968.01 ccw(c356.81,-4925) 382.44,-4967.93 ; 382.3,-4968.01 ccw(c431.81,-4975) 382.28,-4968.18 382.44,-4967.93
OUTPUTN9: P5.6 P9.43 | length 3245.8
  MidLayer1 w10: P9.43@206.81,-4925 280,-4925 ; 281.81,-4925 cw(c281.81,-4975) 307.3,-4931.99 ; 406.18,-4932.07 382.54,-4967.87 cw(c356.81,-4925) 356.81,-4975 cw(c356.81,-4925) 331.08,-4967.87 307.44,-4932.07 ; 406.32,-4931.99 cw(c431.81,-4975) 431.81,-4925 1225,-4925 ccw(c1225,-4876.72) 1259.12,-4910.88 ; 1259.14,-4910.86 1970,-4200 ccw(c1945.86,-4175.86) 1980,-4175.86 1980,-3471.21 cw(c2031.21,-3471.21) 1994.99,-3435.01 2110.01,-3319.99 cw(c2146.21,-3356.21) 2146.21,-3305 ; 2150,-3305 2146.21,-3305 ; P5.6@2310,-3305 2146.21,-3305 ; 307.3,-4931.99 cw(c356.81,-4925) 307.28,-4931.82 307.44,-4932.07 ; 307.3,-4931.99 cw(c281.81,-4975) 307.44,-4932.07
OUTPUTN10: P5.7 P9.44 | length 3225.1
  Bottom Layer w10: P9.44@281.81,-4875 355,-4875 ; 356.81,-4875 ccw(c356.81,-4825) 382.3,-4868.01 ; 481.18,-4867.93 457.54,-4832.13 ccw(c431.81,-4875) 431.81,-4825 ccw(c431.81,-4875) 406.08,-4832.13 382.44,-4867.93 ; 481.32,-4868.01 ccw(c506.81,-4825) 506.81,-4875 1224,-4875 ccw(c1224,-4824.3) 1259.83,-4860.17 1925.17,-4194.83 ccw(c1889.3,-4159) 1940,-4159 1940,-3402 cw(c1990.7,-3402) 1954.83,-3366.17 2110.17,-3210.83 cw(c2146,-3246.7) 2146,-3196 P5.7@2310,-3196 ; 382.3,-4868.01 ccw(c356.81,-4825) 382.44,-4867.93 ; 382.3,-4868.01 ccw(c431.81,-4875) 382.28,-4868.18 382.44,-4867.93
OUTPUTN11: P5.8 P9.45 | length 3365.1
  MidLayer1 w10: P9.45@206.81,-4825 280,-4825 ; 281.81,-4825 cw(c281.81,-4875) 307.3,-4831.99 ; 406.18,-4832.07 382.54,-4867.87 cw(c356.81,-4825) 356.81,-4875 cw(c356.81,-4825) 331.08,-4867.87 307.44,-4832.07 ; 406.32,-4831.99 cw(c431.81,-4875) 431.81,-4825 1235,-4825 ccw(c1235,-4783.96) 1264.01,-4812.99 1867.98,-4209.02 ccw(c1838.96,-4180) 1880,-4180 1880,-3351.21 cw(c1931.21,-3351.21) 1894.99,-3315.01 2107.45,-3102.55 cw(c2145,-3140.11) 2145,-3087 P5.8@2310,-3087 ; 307.3,-4831.99 cw(c356.81,-4825) 307.28,-4831.82 307.44,-4832.07 ; 307.3,-4831.99 cw(c281.81,-4875) 307.44,-4832.07
OUTPUTN12: P5.9 P9.46 | length 3349
  Bottom Layer w10: P9.46@281.81,-4775 355,-4775 ; 356.81,-4775 ccw(c356.81,-4725) 382.3,-4768.01 ; 481.18,-4767.93 457.54,-4732.13 ccw(c431.81,-4775) 431.81,-4725 ccw(c431.81,-4775) 406.08,-4732.13 382.44,-4767.93 ; 481.32,-4768.01 ccw(c506.81,-4725) 506.81,-4775 1234,-4775 ccw(c1234,-4724.3) 1269.83,-4760.17 1825.17,-4204.83 ccw(c1789.3,-4169) 1840,-4169 1840,-3284 cw(c1890.7,-3284) 1854.83,-3248.17 2110.17,-2992.83 cw(c2146,-3028.7) 2146,-2978 P5.9@2310,-2978 ; 382.3,-4768.01 ccw(c356.81,-4725) 382.44,-4767.93 ; 382.3,-4768.01 ccw(c431.81,-4775) 382.28,-4768.18 382.44,-4767.93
